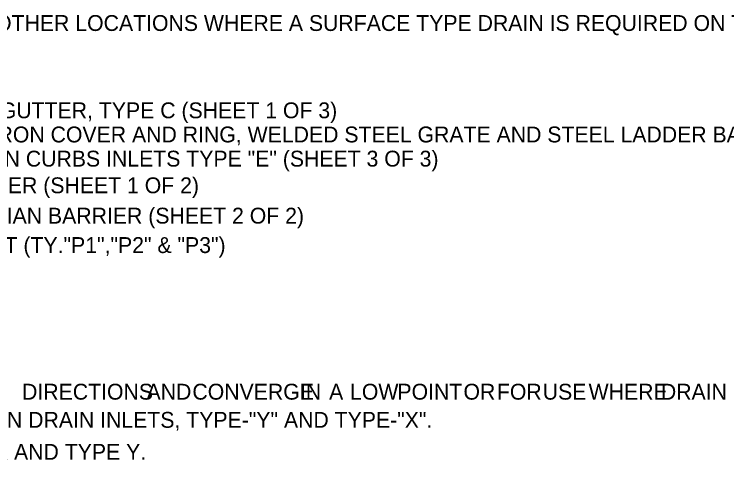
# Model space of a CAD drawing. Extents: x -12822 to 16384, y -6351 to 1913.
# Drawn here: x 46 to 494.7, y -1535.7 to -1253.1 of the extents above; entities that cross this region are included whole.
import ezdxf

# ---------------------------------------------------------------- set-up
doc = ezdxf.new("R2010")
doc.units = 0
doc.layers.add('Level 10', color=7, linetype='Continuous')

msp = doc.modelspace()

# ---------------------------------------------------------------- texts
at = {"layer": 'Level 10'}
for s, p in [('SEWER INLET TYPE-B (SURFACE DRAIN) THIS INLET IS FOR USE IN INTERSECTIONS AND OTHER LOCATIONS WHERE A SURFACE TYPE DRAIN IS REQUIRED ON THE TRAVEL WAY (SHEET 2 OF 2)', (-550.79, -1263.63)), ('DETAILS OF CURB INLET-TYPE E FOR USE WITH TYPE N CURB OR COMBINATION CURB & GUTTER, TYPE C (SHEET 1 OF 3)', (-550.79, -1318.64)), ('DETAILS OF CAST DUCTILE OR MALLEABLE IRON GRATE SEAT, CAST DUCTILE OR GRAY IRON COVER AND RING, WELDED STEEL GRATE AND STEEL LADDER BARS FOR CURB INLETS, TYPE "E" (SHEET 2 OF 3)', (-550.79, -1333.86)), ('DETAILS OF WELDED FRAME No CIGS-20 & STEEL WELDED CURVED VANE GRATE USED ON CURBS INLETS TYPE "E" (SHEET 3 OF 3)', (-550.79, -1349.09)), ('DETAILS OF INLET-TYPE E-3 AND E-4 FOR USE WITH 2\' -6" WIDE CONCRETE MEDIAN BARRIER (SHEET 1 OF 2)', (-550.79, -1365.89)), ('DETAILS OF PRECAST INLET TYPE E-3 AND E-4 FOR USE WITH 2\' -6" WIDE CONCRETE MEDIAN BARRIER (SHEET 2 OF 2)', (-550.79, -1385.01)), ('DETAIL OF CIRCULAR PRECAST CONCRETE AND BRICK OR CONCRETE BLOCK DROP INLET (TY."P1","P2" & "P3")', (-550.79, -1403.55)), (' DIRECTIONS', (47.21, -1495.94)), (' AND', (125.61, -1495.94)), (' CONVERGE', (154.49, -1495.94)), (' IN', (222.25, -1495.94)), (' A', (240.57, -1495.94)), (' LOW', (253.77, -1495.94)), (' POINT', (283.61, -1495.94)), (' OR', (325.21, -1495.94)), (' FOR', (346.25, -1495.94)), (' USE', (375.13, -1495.94)), (' WHERE', (404.01, -1495.94)), (' DRAIN', (449.53, -1495.94)), ('DETAILS OF DUCTILE OR MALLEABLE IRON GRATE CASTINGS FOR USE ON SAFETY MEDIAN DRAIN INLETS, TYPE-"Y" AND TYPE-"X".', (-550.79, -1513.68)), ('DETAILS OF WELDED STEEL GRATES FOR USE ON SAFETY MEDIAN DRAIN INLETS, TYPE X AND TYPE Y.', (-550.79, -1533.85))]:
    msp.add_text(s, height=10, dxfattribs=at).set_placement(p)

doc.saveas('drawing.dxf')
